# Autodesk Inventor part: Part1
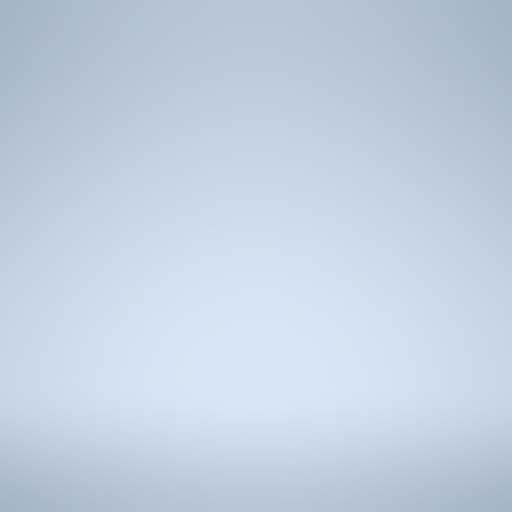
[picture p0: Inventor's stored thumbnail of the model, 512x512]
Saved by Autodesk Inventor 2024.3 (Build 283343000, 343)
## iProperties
Created: 2024-12
Part Number: Part1
Material: Generic
Document SubType Name: Modeling
Designer: ruhr
Density: 1 g/cm^3
Appearance: Default
Author: ruhr
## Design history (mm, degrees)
sketch "Sketch1"
  geometry: C1 r 6.137 at (0, 0); 1 further point
  constraints: 1 centre point, 1 coincident
  dimensions: "d0" = 10 dimension on point (0, 0) C1.centre C1
extrude "Extrusion1" new body sketch "Sketch1" distance "d0" = 10; taper "d1" = 0 deg
body "Solid1"
